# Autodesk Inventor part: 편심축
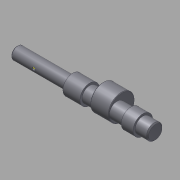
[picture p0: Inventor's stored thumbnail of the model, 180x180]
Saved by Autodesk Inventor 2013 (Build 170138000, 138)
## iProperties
Company: 한국ATC센터
Created: 2015-12
Part Number: 편심축
Document SubType Name: Modeling
Designer: mdu
Density: 7.86 g/cm^3
Mass: 225.292 g
Surface Area: 81.2409 cm^2
Volume: 28.6631 cm^3
Material: 강철, 연강
Author: mdu
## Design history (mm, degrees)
sketch "스케치1"
  geometry: L1 (-86, 0)-(86, 0); L2 (-86, 0)-(-86, 6); L3 (-86, 6)-(-32, 6); L4 (-32, 6)-(-32, 9.5); L5 (-32, 9.5)-(-15.5, 9.5); L6 (-15.5, 9.5)-(-15.5, 7.5); L7 (-15.5, 7.5)-(48, 7.5); L8 (86, 6)-(86, 0); L9 (36, 7.5)-(36, 9.5); L10 (36, 9.5)-(24.5, 9.5); L11 (24.5, 9.5)-(24.5, 7.5); L12 (48, 7.5)-(48, 6); L13 (48, 6)-(86, 6); 2 further points
  constraints: 26 end point, 6 parallel, 6 perpendicular, 2 point on line, 1 coincident, 1 horizontal, 1 midpoint
  dimensions: "d1" = 12 diameter of L3 L1; "d2" = 15 diameter of L7 L1; "d4" = 16.5 distance of L4.end L5.end; "d5" = 19 diameter of L5 L1; "d24" = 11.5 distance of L9.end L10.end; "d25" = 19 diameter of L10 L1; "d27" = 40 distance between parallel lines of L11 L6; "d28" = 54 distance of L2.end L3.end; "d29" = 50 distance between parallel lines of L8 L9; "d41" = 38 distance between parallel lines of L8 L12; "d42" = 12 diameter of L13 L1
revolve "회전1" stored, may be unused: angle "d6" = 90 deg
node "작업 평면1"
sketch "스케치2"
  geometry: C1 r 7.5 at (0, 0) reference; C2 r 12.5 at (0, 4.5); 1 further point
  constraints: 1 centre point, 1 vertical alignment
  dimensions: "d8" = 4.5 distance of point (0, 0) C2.centre; "d9" = 25 diameter of C2
extrude "돌출1" join sketch "스케치2" distance "d10" = 18; taper "d11" = 0 deg
chamfer "모따기1" distance "d12" = 1; stored, may be unused: second distance "d13" = 2, angle "d14" = 45 deg
chamfer "모따기2" distance "d15" = 0.5; stored, may be unused: second distance "d16" = 2, angle "d17" = 45 deg
node "작업 평면2"
sketch "스케치3"
  geometry: L1 (4, -2)-(18, -2); L2 (18, 2)-(4, 2); L3 (27, 5)-(27, -5) reference; A1 r 2 centre (18, 0) between (18, -2) and (18, 2); A2 r 2 centre (4, 0) between (4, 2) and (4, -2); 2 further points
  constraints: 4 end point, 4 point on circle, 4 tangent, 2 centre point, 1 horizontal, 1 horizontal alignment, 1 midpoint, 1 parallel
  dimensions: "d18" = 7 distance edge to line of A1 L3; "d19" = 4 distance between parallel lines of L2 L1; "d20" = 18 dimension on A1 A2
extrude "돌출2" cut sketch "스케치3" distance "d21" = 2.5; taper "d22" = 0 deg
revolve "회전2" stored, may be unused: angle "d26" = 90 deg
node "작업 평면3"
sketch "스케치4"
  geometry: L1 (44, 5)-(44, -5) reference; 2 further points
  constraints: 1 horizontal alignment
  dimensions: "d30" = 12 distance from line of point (32, 0) L1
hole "구멍1" sketch "스케치4" at (32, 0) diameter "d31" = 6; stored, may be unused: countersink angle "d35" = 90 deg, drill point angle "d37" = 118 deg; dims "d32" = 6, "d33" = 14, "d34" = 3, "d36" = 8
node "작업 평면4"
sketch "스케치5"
  geometry: C1 r 3 at (32, 0) reference; C2 r 8 at (32, 0); 2 further points
  constraints: 1 centre point, 1 coincident, 1 other
  dimensions: "d38" = 16 diameter of C2
extrude "돌출3" cut sketch "스케치5" distance "d39" = 3; taper "d40" = 0 deg
sketch "스케치6"
  geometry: L1 (-85, -6)-(-32, -6) reference; L2 (-86, -5)-(-86, 5) reference; L3 (-85, 6)-(-32, 6) reference; L4 (-64, 6)-(-64, -6); L5 (-64, -6)-(-62.5, -6); L6 (-64, -4.5)-(-62.5, -6); L7 (-64, -6)-(-64, -4.5); 2 further points
  constraints: 8 end point, 4 point on line, 2 perpendicular, 1 coincident
  dimensions: "d43" = 22 distance between parallel lines of L4 L2; "d44" = 45 deg angle of L6 L7; "d45" = 3 diameter of L5.end L4
revolve "회전3" stored, may be unused: angle "d46" = 90 deg
node "작업점1"
chamfer "모따기3" distance "d47" = 0.5; stored, may be unused: second distance "d48" = 2, angle "d49" = 45 deg
sketch "스케치7"
  geometry: C1 r 7.5 at (0, 0) reference; 1 further point
extrude "돌출4" cut sketch "스케치7" stored distance "d50" = 10; taper "d51" = 0 deg
chamfer "모따기4" distance "d52" = 1; stored, may be unused: second distance "d53" = 2, angle "d54" = 45 deg
node "작업 평면5"
node "솔리드1"
node "투영된 루프1"
other parameters: "d7" = 8.5
